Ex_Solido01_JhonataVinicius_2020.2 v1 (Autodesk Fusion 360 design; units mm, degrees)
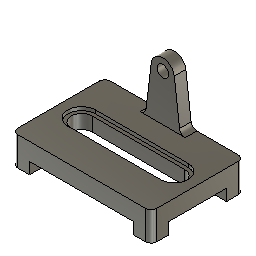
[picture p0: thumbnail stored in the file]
sketch "Sketch1" plane through (0, 0, 0) normal (0, 0, 1) x axis (1, 0, 0)
  line L1 (60, 40) -> (-60, 40)
  line L2 (60, -40) -> (60, 40)
  line L3 (-60, -40) -> (60, -40)
  line L4 (-60, 40) -> (-60, -40)
  line L5 (60, -40) -> (-60, 40)
  line L6 (-60, -40) -> (60, 40)
  line L7 (60, 0) -> (-60, 0)
  line L8 (0, -40) -> (0, 40)
  line L9 (40, -12) -> (-40, -12)
  line L10 (-40, 12) -> (40, 12)
  line L11 (40, 0) -> (-40, 0)
  line L12 (40, -9) -> (-40, -9)
  line L13 (-40, 9) -> (40, 9)
  arc A1 centre (40, 0) radius 12 clockwise from (40, 12) to (40, -12)
  arc A2 centre (-40, 0) radius 12 clockwise from (-40, -12) to (-40, 12)
  arc A3 centre (40, 0) radius 9 clockwise from (40, 9) to (40, -9)
  arc A4 centre (-40, 0) radius 9 clockwise from (-40, -9) to (-40, 9)
  point P6 (0, 0)
  point P1 (0, 0)
  point P8 (60, 0)
  point P10 (0, -40)
  point P16 (40, 0)
  point P4 (60, -40)
  point P5 (-60, -40)
  point P3 (60, 40)
  point P15 (-40, 0)
  horizontal L1
  perpendicular L1 L2
  parallel L1 L3
  parallel L2 L4
  coincident L5 P6
  coincident L6 P6
  coincident P1 P6
  perpendicular L4 L7
  midpoint L2 P8
  vertical L8
  midpoint L3 P10
  tangent L9 A1
  tangent A1 L10
  parallel L9 L10
  tangent L10 A2
  tangent L9 A2
  coincident L7 P16
  parallel L7 L11
  dimension "d1" distance P4 P5 = 120
  dimension "d2" distance P3 P4 = 80
  dimension "d3" diameter A1 = 24
  dimension "d4" distance P1 P16 = 40
  dimension "d5" distance P6 P15 = 40
  dimension "d6" = -3
  dimension "d7" distance P8 P16 = 20
extrude "Extrude1" new body sketch "Sketch1" profile of L1 L2 L3 L4 L9 A1 L10 A2 A4 L12 A3 L13 along normal blind 25
extrude "Extrude2" sketch "Sketch1" profile of L9 A1 L10 A2 A4 L12 A3 L13 blind -3
sketch "Sketch2" plane through (0, 0, 0) normal (0, 0, -1) x axis (1, 0, 0)
  line L1 (40, 9) -> (-40, 9)
  line L2 (-40, -9) -> (40, -9)
  line L3 (-60, 40) -> (60, 40)
  line L4 (-60, -40) -> (-60, 40)
  line L5 (60, -40) -> (-60, -40)
  line L6 (60, 40) -> (60, -40)
  line L7 (-45, 25) -> (-60, 25)
  line L8 (-45, 40) -> (-45, 25)
  line L9 (45, 25) -> (45, 40)
  line L10 (60, 25) -> (45, 25)
  line L11 (-45, -25) -> (-60, -25)
  line L12 (-45, -40) -> (-45, -25)
  line L13 (45, -25) -> (60, -25)
  line L14 (45, -40) -> (45, -25)
  arc A1 centre (-40, 0) radius 9 clockwise from (-40, -9) to (-40, 9)
  arc A2 centre (40, 0) radius 9 clockwise from (40, 9) to (40, -9)
  point P12 (-60, 25)
  point P14 (-45, 40)
  point P15 (45, 40)
  point P17 (60, 25)
  point P18 (-60, -25)
  point P20 (-45, -40)
  point P21 (60, -25)
  point P23 (45, -40)
  coincident L4 P12
  perpendicular L4 L7
  coincident L3 P14
  perpendicular L3 L8
  coincident L3 P15
  perpendicular L3 L9
  coincident L6 P17
  perpendicular L6 L10
  coincident L4 P18
  perpendicular L4 L11
  coincident L5 P20
  perpendicular L5 L12
  coincident L6 P21
  perpendicular L6 L13
  coincident L5 P23
  perpendicular L5 L14
  dimension "d15" distance L3 L7 = 15
  dimension "d16" distance L4 L8 = 15
  dimension "d17" distance L5 L11 = 15
  dimension "d18" distance L4 L12 = 15
  dimension "d19" distance L6 L14 = 15
  dimension "d20" distance L5 L13 = 15
  dimension "d21" distance L6 L9 = 15
  dimension "d22" distance L3 L10 = 15
extrude "Extrude3" cut sketch "Sketch2" against normal blind 10
sketch "Sketch3" plane through (0, 40, 0) normal (0, 1, 0) x axis (-1, 0, 0)
  line L1 (45, 0) -> (45, 10)
  line L2 (60, 0) -> (45, 0)
  line L3 (60, 25) -> (60, 0)
  line L4 (-60, 25) -> (60, 25)
  line L5 (-60, 0) -> (-60, 25)
  line L6 (-45, 0) -> (-60, 0)
  line L7 (-45, 10) -> (-45, 0)
  line L8 (45, 10) -> (-45, 10)
  line L9 (0, 75) -> (0, 25)
  line L10 (25, 65) -> (-25, 65)
  line L11 (9.9251, 66.2219) -> (15, 25)
  line L12 (-9.9251, 66.2219) -> (-15, 25)
  circle C1 centre (0, 65) radius 5
  arc A1 centre (0, 65) radius 10 clockwise from (-9.9251, 66.2219) to (9.9251, 66.2219)
  point P10 (0, 25)
  point P14 (0, 65)
  point P16 (15, 25)
  point P17 (-15, 25)
  point P15 (0, 65)
  midpoint L4 P10
  perpendicular L4 L9
  perpendicular L9 L10
  midpoint L10 P14
  concentric C1 A1
  coincident L4 P16
  coincident L4 P17
  tangent L12 A1
  tangent L11 A1
  coincident L9 P15
  dimension "d25" distance L4 L10 = 40
  dimension "d26" diameter C1 = 10
  dimension "d27" diameter A1 = 20
  dimension "d28" distance P10 P16 = 15
  dimension "d30" distance P10 P17 = 15
extrude "Extrude4" add sketch "Sketch3" profile of L4 C1 A1 L11 L12 against normal blind 10
fillet "Fillet1" radius 5
fillet "Fillet2" radius 5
